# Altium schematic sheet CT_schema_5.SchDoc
size 514 x 379 mm
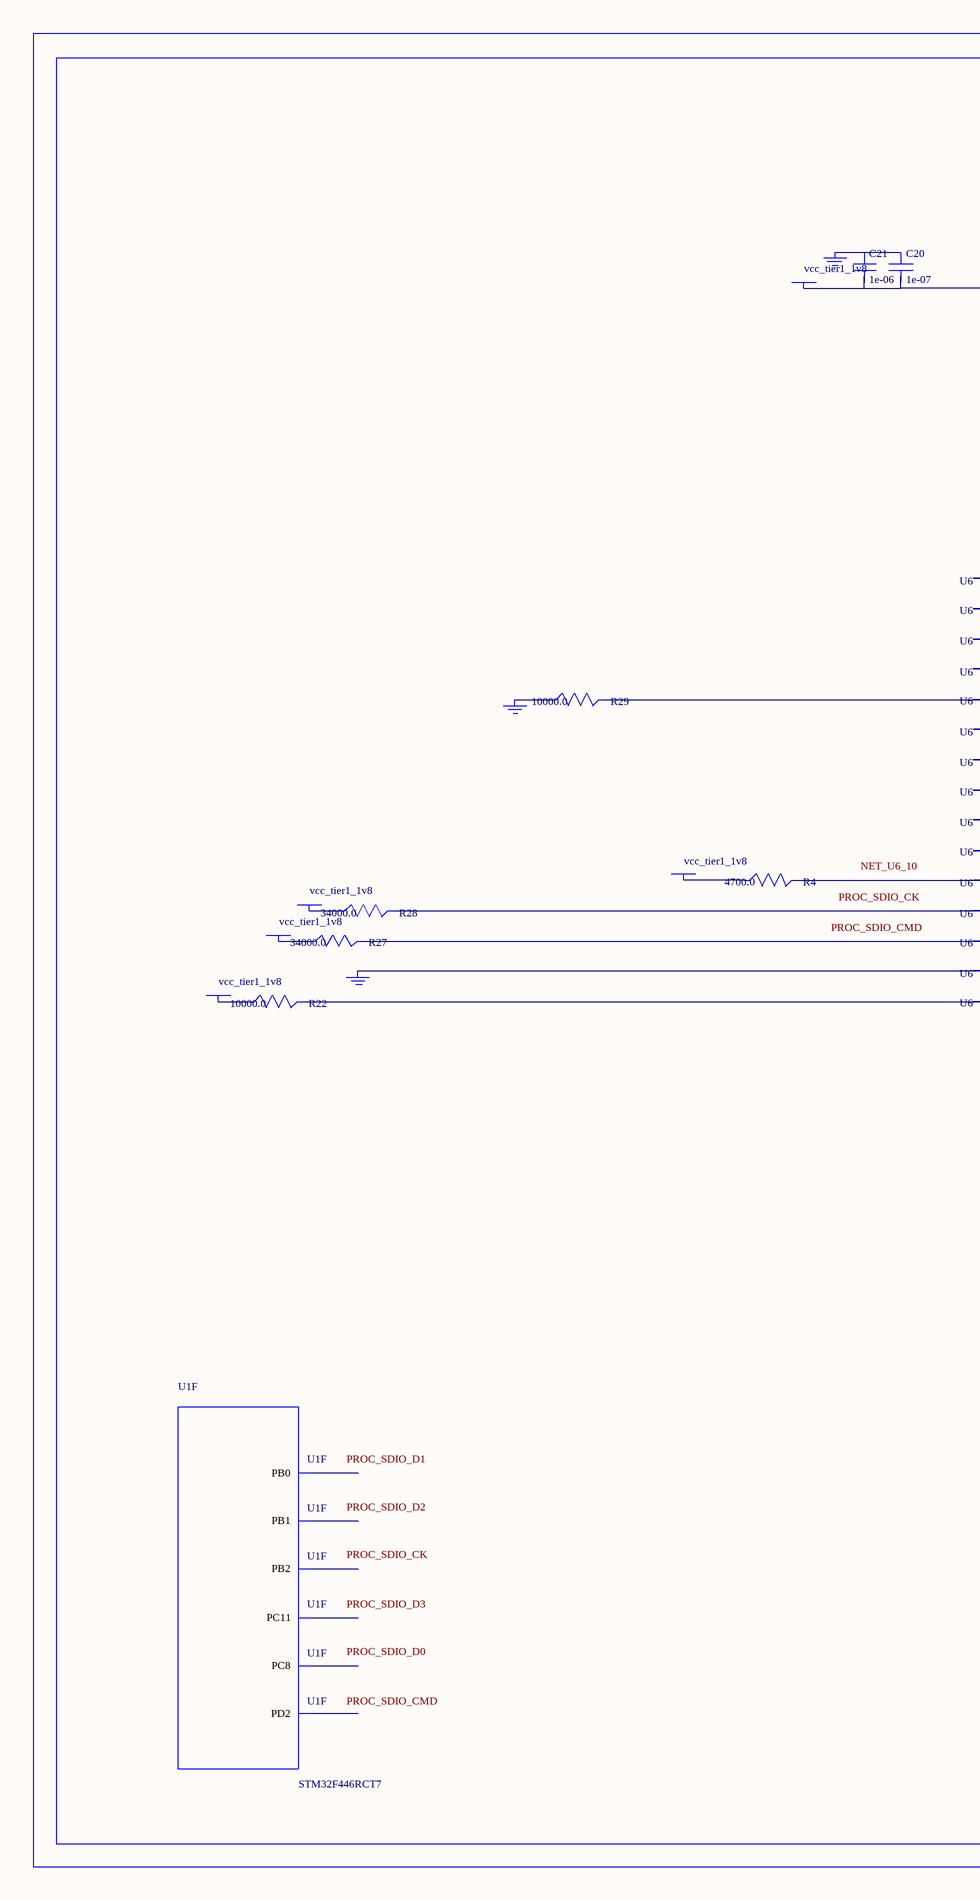
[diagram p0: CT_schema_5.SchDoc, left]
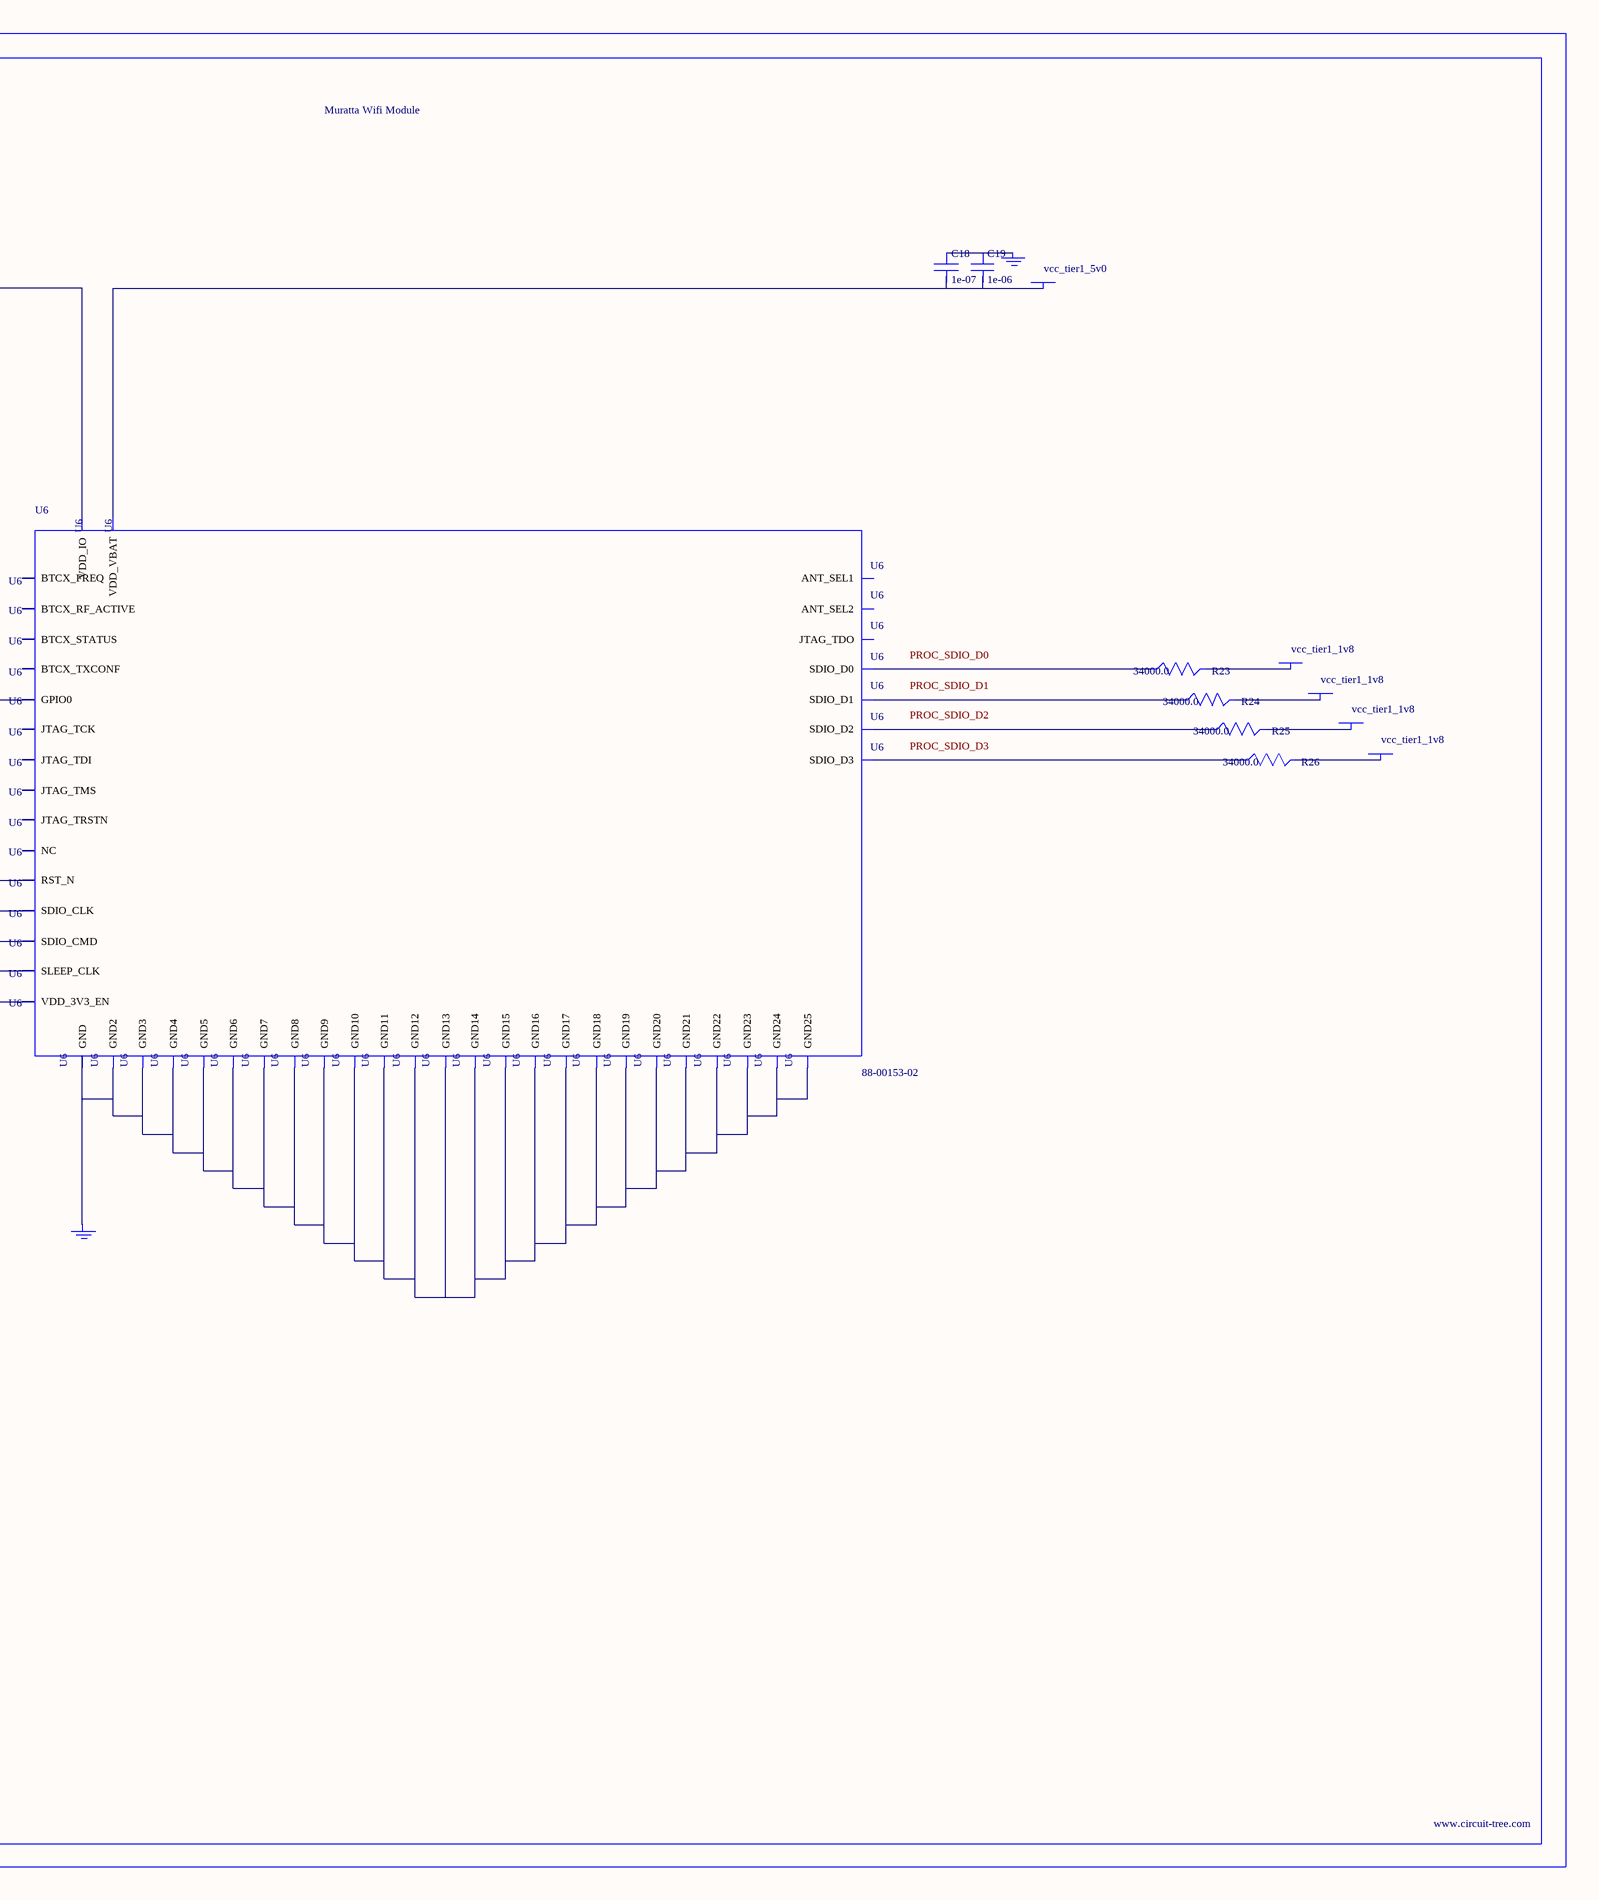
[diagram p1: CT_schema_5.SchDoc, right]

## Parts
BORDER4  (no value)
C18  1e-07  [C0402]
C19  1e-06  [C0603]
C20  1e-07  [C0402]
C21  1e-06  [C0603]
GND_INSTANCE_4_0  (no value)
GND_INSTANCE_4_1  (no value)
GND_INSTANCE_4_2  (no value)
GND_INSTANCE_4_3  (no value)
GND_INSTANCE_4_4  (no value)
POWER_INSTANCE_4_0  vcc_tier1_1v8
POWER_INSTANCE_4_1  vcc_tier1_1v8
POWER_INSTANCE_4_2  vcc_tier1_5v0
POWER_INSTANCE_4_3  vcc_tier1_1v8
POWER_INSTANCE_4_4  vcc_tier1_1v8
POWER_INSTANCE_4_5  vcc_tier1_1v8
POWER_INSTANCE_4_6  vcc_tier1_1v8
POWER_INSTANCE_4_7  vcc_tier1_1v8
POWER_INSTANCE_4_8  vcc_tier1_1v8
POWER_INSTANCE_4_9  vcc_tier1_1v8
R4  4700.0  [R0603]
R22  10000.0  [R0603]
R23  34000.0  [R0603]
R24  34000.0  [R0603]
R25  34000.0  [R0603]
R26  34000.0  [R0603]
R27  34000.0  [R0603]
R28  34000.0  [R0603]
R29  10000.0  [R0603]
U1  STM32F446RCT7  [LQFP64]  (part F of 7)
U6  88-00153-02  [88-00153-02]

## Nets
NetC18_1: C18.1 C19.1 GND_INSTANCE_4_1.0(GND)
NetC18_2: C18.2 C19.2 POWER_INSTANCE_4_2.0(PWR) U6.12(VDD_VBAT)
NetC20_1: C20.1 C21.1 GND_INSTANCE_4_3.0(GND)
NetC20_2: C20.2 C21.2 POWER_INSTANCE_4_3.0(PWR) U6.33(VDD_IO)
NetGND_INSTANCE_4_0_0: GND_INSTANCE_4_0.0(GND) R29.1
NetGND_INSTANCE_4_2_0: GND_INSTANCE_4_2.0(GND) U6.31(SLEEP_CLK)
NetGND_INSTANCE_4_4_0: GND_INSTANCE_4_4.0(GND) U6.1(GND) U6.9(GND2) U6.13(GND3) U6.14(GND4) U6.15(GND5) U6.16(GND6) U6.17(GND7) U6.18(GND8) U6.19(GND9) U6.20(GND10) U6.21(GND11) U6.22(GND12) U6.23(GND13) U6.24(GND14) U6.25(GND15) U6.26(GND16) U6.27(GND17) U6.32(GND18) U6.39(GND19) U6.40(GND20) U6.41(GND21) U6.42(GND22) U6.43(GND23) U6.44(GND24) U6.49(GND25)
NetPOWER_INSTANCE_4_0_0: POWER_INSTANCE_4_0.0(PWR) R25.2
NetPOWER_INSTANCE_4_1_0: POWER_INSTANCE_4_1.0(PWR) R22.1
NetPOWER_INSTANCE_4_4_0: POWER_INSTANCE_4_4.0(PWR) R24.2
NetPOWER_INSTANCE_4_5_0: POWER_INSTANCE_4_5.0(PWR) R23.2
NetPOWER_INSTANCE_4_6_0: POWER_INSTANCE_4_6.0(PWR) R28.1
NetPOWER_INSTANCE_4_7_0: POWER_INSTANCE_4_7.0(PWR) R27.1
NetPOWER_INSTANCE_4_8_0: POWER_INSTANCE_4_8.0(PWR) R26.2
NetPOWER_INSTANCE_4_9_0: POWER_INSTANCE_4_9.0(PWR) R4.1
NetR4_2: R4.2 U6.10(RST_N)
NetR22_2: R22.2 U6.11(VDD_3V3_EN)
NetR23_1: R23.1 U6.35(SDIO_D0)
NetR24_1: R24.1 U6.34(SDIO_D1)
NetR25_1: R25.1 U6.2(SDIO_D2)
NetR26_1: R26.1 U6.38(SDIO_D3)
NetR27_2: R27.2 U6.37(SDIO_CMD)
NetR28_2: R28.2 U6.36(SDIO_CLK)
NetR29_2: R29.2 U6.6(GPIO0)

Not connected (* = marked no-connect by the designer): U1 26(PB0) 27(PB1) 28(PB2) 39(PC8) 52(PC11) 54(PD2); U6 3(JTAG_TDI) 4(JTAG_TDO) 5(BTCX_FREQ) 7(ANT_SEL2) 8(ANT_SEL1) 28(BTCX_STATUS) 29(BTCX_TXCONF) 30(BTCX_RF_ACTIVE) 45(JTAG_TCK) 46(JTAG_TRSTN) 47(JTAG_TMS) 48(NC)

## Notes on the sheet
- Labels drawn without touching a wire or pin: NET_U6_10, PROC_SDIO_CK, PROC_SDIO_CMD, PROC_SDIO_D0, PROC_SDIO_D1, PROC_SDIO_D2, PROC_SDIO_D3

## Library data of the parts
BORDER4 = BORDER_PAGE4
C18 C20 = C0402C104K3RACTU
C19 C21 = C0603C105K3RACTU
GND_INSTANCE_4_0-GND_INSTANCE_4_4 = GND
POWER_INSTANCE_4_0-POWER_INSTANCE_4_9 = PWR
R4 = RC0603JR-074K7L
R22 R29 = RC0603JR-0710KL
R23-R28 = ERA3ARB3402V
